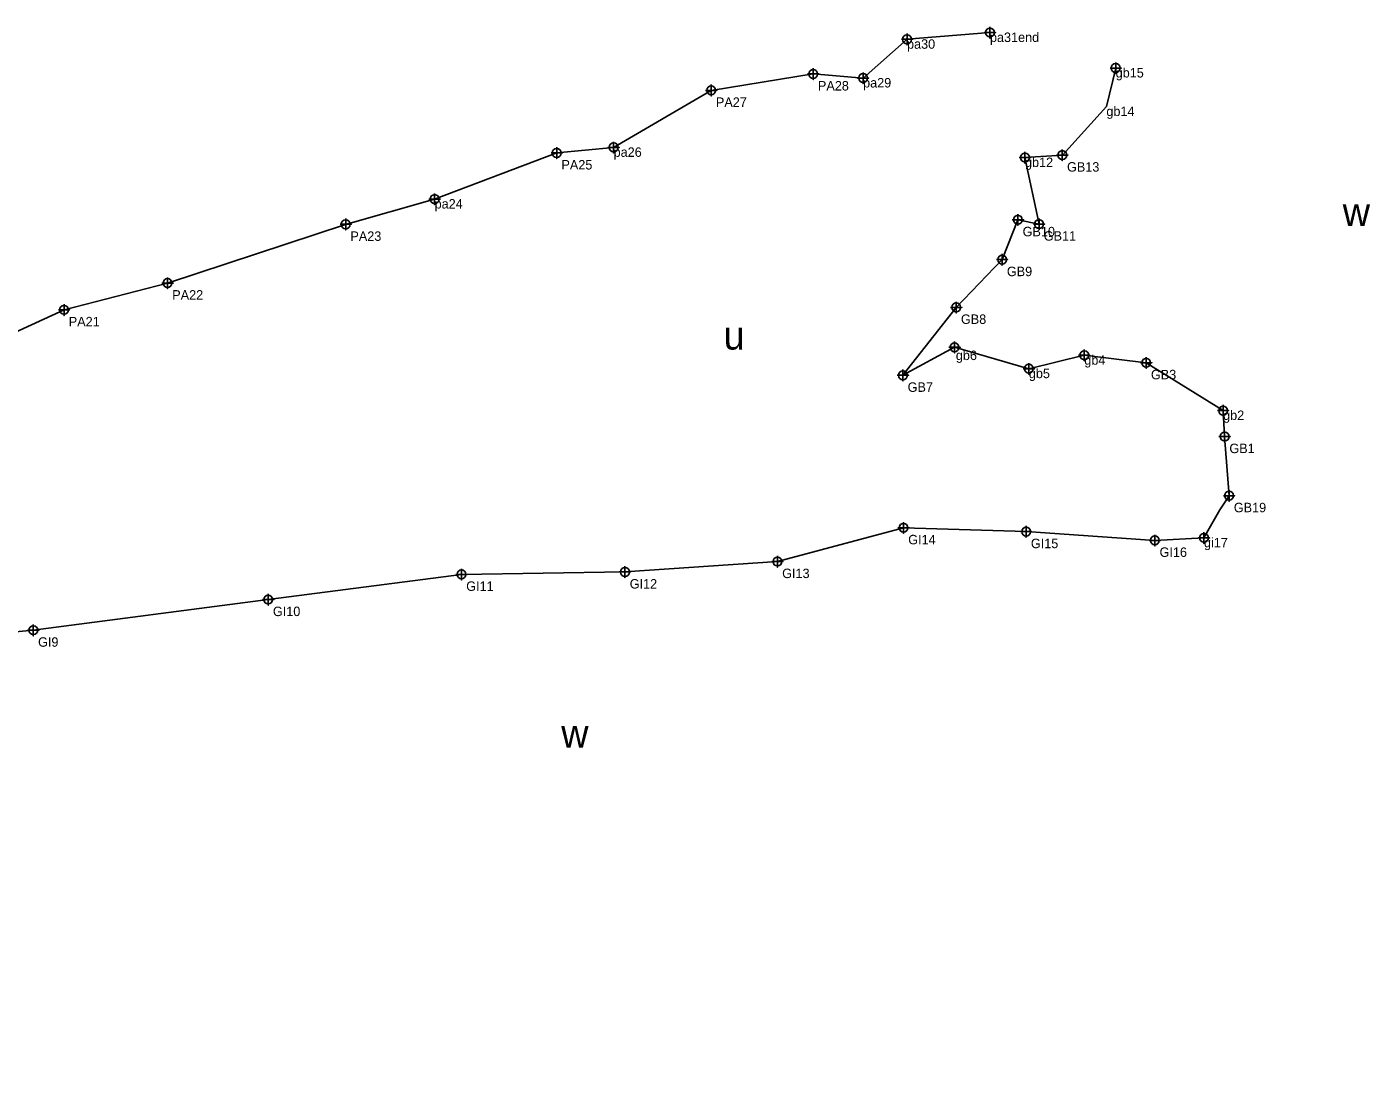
# Model space of a CAD drawing. Extents: x 2184390 to 2187551, y 452846 to 453752.
# Drawn here: x 2186840 to 2187551, y 453193 to 453752 of the extents above; entities that cross this region are included whole.
import ezdxf

# ---------------------------------------------------------------- set-up
doc = ezdxf.new("R2010")
doc.units = 0
for name, color, linetype in [('Exist Environmental Wetland Boundary', 7, 'Continuous'), ('Exist Environmental Wetland Boundary Cogo Comment', 7, 'Continuous'), ('Exist Environmental Wetland Boundary Cogo Point CELL', 7, 'Continuous'), ('Old_Level_20', 7, 'Continuous'), ('Old_Level_52', 7, 'Continuous')]:
    doc.layers.add(name, color=color, linetype=linetype)

msp = doc.modelspace()

# ---------------------------------------------------------------- linework, layer by layer
at = {"layer": 'Exist Environmental Wetland Boundary'}
for points in [[(2186825.25, 453586.6), (2186859.95, 453602.41), (2186914.68, 453616.56), (2187008.89, 453647.61), (2187055.94, 453660.98), (2187120.52, 453685.38), (2187150.61, 453688.32), (2187202.21, 453718.49), (2187256.17, 453727.15), (2187282.56, 453725), (2187305.8, 453745.49), (2187349.64, 453749.06)], [(2187476.13, 453504.11), (2187473.78, 453535.38), (2187472.97, 453549.14), (2187432.29, 453574.42), (2187399.56, 453578.39), (2187370.22, 453571.28), (2187330.92, 453582.59), (2187303.63, 453567.79), (2187331.81, 453603.71), (2187356.1, 453628.96), (2187364.42, 453650.04), (2187375.61, 453647.76), (2187368.19, 453682.93), (2187387.95, 453684.27), (2187411.24, 453709.91), (2187416.15, 453730.28)], [(2186590.17, 453193.44), (2186576.37, 453212.42), (2186571.99, 453259.45), (2186574.44, 453309.06), (2186581.86, 453375.55), (2186597.55, 453411.45), (2186689.52, 453421.44), (2186746.86, 453423.8), (2186843.7, 453432.98), (2186967.92, 453449.19), (2187070.14, 453462.52), (2187156.63, 453463.76), (2187237.25, 453469.29), (2187303.93, 453487.14), (2187368.79, 453485.11), (2187436.86, 453480.5), (2187462.85, 453481.82), (2187471.15, 453496.67), (2187476.13, 453504.11)]]:
    msp.add_lwpolyline(points, dxfattribs=at)
at = {"layer": 'Exist Environmental Wetland Boundary Cogo Point CELL'}
for points in [[(2187349.64, 453752.06), (2187349.64, 453746.06), (2187349.64, 453749.06), (2187352.64, 453749.06), (2187346.64, 453749.06)], [(2187305.8, 453748.49), (2187305.8, 453742.49), (2187305.8, 453745.49), (2187308.8, 453745.49), (2187302.8, 453745.49)], [(2187256.17, 453730.15), (2187256.17, 453724.15), (2187256.17, 453727.15), (2187259.17, 453727.15), (2187253.17, 453727.15)], [(2187416.15, 453733.28), (2187416.15, 453727.28), (2187416.15, 453730.28), (2187419.15, 453730.28), (2187413.15, 453730.28)], [(2187282.56, 453728), (2187282.56, 453722), (2187282.56, 453725), (2187285.56, 453725), (2187279.56, 453725)], [(2187202.21, 453721.49), (2187202.21, 453715.49), (2187202.21, 453718.49), (2187205.21, 453718.49), (2187199.21, 453718.49)], [(2187120.52, 453688.38), (2187120.52, 453682.38), (2187120.52, 453685.38), (2187123.52, 453685.38), (2187117.52, 453685.38)], [(2187150.61, 453691.32), (2187150.61, 453685.32), (2187150.61, 453688.32), (2187153.61, 453688.32), (2187147.61, 453688.32)], [(2187387.92, 453687.25), (2187387.92, 453681.25), (2187387.92, 453684.25), (2187390.92, 453684.25), (2187384.92, 453684.25)], [(2187368.19, 453685.93), (2187368.19, 453679.93), (2187368.19, 453682.93), (2187371.19, 453682.93), (2187365.19, 453682.93)], [(2187055.94, 453663.98), (2187055.94, 453657.98), (2187055.94, 453660.98), (2187058.94, 453660.98), (2187052.94, 453660.98)], [(2187364.43, 453653.05), (2187364.43, 453647.05), (2187364.43, 453650.05), (2187367.43, 453650.05), (2187361.43, 453650.05)], [(2187008.9, 453650.63), (2187008.9, 453644.63), (2187008.9, 453647.63), (2187011.9, 453647.63), (2187005.9, 453647.63)], [(2187375.61, 453650.76), (2187375.61, 453644.76), (2187375.61, 453647.76), (2187378.61, 453647.76), (2187372.61, 453647.76)], [(2187356.1, 453631.96), (2187356.1, 453625.96), (2187356.1, 453628.96), (2187359.1, 453628.96), (2187353.1, 453628.96)], [(2186914.68, 453619.56), (2186914.68, 453613.56), (2186914.68, 453616.56), (2186917.68, 453616.56), (2186911.68, 453616.56)], [(2186859.95, 453605.41), (2186859.95, 453599.41), (2186859.95, 453602.41), (2186862.95, 453602.41), (2186856.95, 453602.41)], [(2187331.81, 453606.71), (2187331.81, 453600.71), (2187331.81, 453603.71), (2187334.81, 453603.71), (2187328.81, 453603.71)], [(2187330.92, 453585.58), (2187330.92, 453579.58), (2187330.92, 453582.58), (2187333.92, 453582.58), (2187327.92, 453582.58)], [(2187399.56, 453581.39), (2187399.56, 453575.39), (2187399.56, 453578.39), (2187402.56, 453578.39), (2187396.56, 453578.39)], [(2187370.22, 453574.28), (2187370.22, 453568.28), (2187370.22, 453571.28), (2187373.22, 453571.28), (2187367.22, 453571.28)], [(2187432.29, 453577.42), (2187432.29, 453571.42), (2187432.29, 453574.42), (2187435.29, 453574.42), (2187429.29, 453574.42)], [(2187303.62, 453570.79), (2187303.62, 453564.79), (2187303.62, 453567.79), (2187306.62, 453567.79), (2187300.62, 453567.79)], [(2187472.98, 453552.11), (2187472.98, 453546.11), (2187472.98, 453549.11), (2187475.98, 453549.11), (2187469.98, 453549.11)], [(2187473.78, 453538.38), (2187473.78, 453532.38), (2187473.78, 453535.38), (2187476.78, 453535.38), (2187470.78, 453535.38)], [(2187476.13, 453507.11), (2187476.13, 453501.11), (2187476.13, 453504.11), (2187479.13, 453504.11), (2187473.13, 453504.11)], [(2187303.93, 453490.14), (2187303.93, 453484.14), (2187303.93, 453487.14), (2187306.93, 453487.14), (2187300.93, 453487.14)], [(2187368.79, 453488.11), (2187368.79, 453482.11), (2187368.79, 453485.11), (2187371.79, 453485.11), (2187365.79, 453485.11)], [(2187436.86, 453483.5), (2187436.86, 453477.5), (2187436.86, 453480.5), (2187439.86, 453480.5), (2187433.86, 453480.5)], [(2187462.85, 453484.82), (2187462.85, 453478.82), (2187462.85, 453481.82), (2187465.85, 453481.82), (2187459.85, 453481.82)], [(2187156.63, 453466.76), (2187156.63, 453460.76), (2187156.63, 453463.76), (2187159.63, 453463.76), (2187153.63, 453463.76)], [(2187237.25, 453472.29), (2187237.25, 453466.29), (2187237.25, 453469.29), (2187240.25, 453469.29), (2187234.25, 453469.29)], [(2187070.14, 453465.52), (2187070.14, 453459.52), (2187070.14, 453462.52), (2187073.14, 453462.52), (2187067.14, 453462.52)], [(2186967.92, 453452.19), (2186967.92, 453446.19), (2186967.92, 453449.19), (2186970.92, 453449.19), (2186964.92, 453449.19)], [(2186843.7, 453435.98), (2186843.7, 453429.98), (2186843.7, 453432.98), (2186846.7, 453432.98), (2186840.7, 453432.98)]]:
    msp.add_lwpolyline(points, dxfattribs=at)
for centre in [(2187349.64, 453749.06), (2187305.8, 453745.49), (2187416.15, 453730.28), (2187256.17, 453727.15), (2187282.56, 453725), (2187202.21, 453718.49), (2187120.52, 453685.38), (2187150.61, 453688.32), (2187368.19, 453682.93), (2187387.92, 453684.25), (2187055.94, 453660.98), (2187364.43, 453650.05), (2187008.9, 453647.63), (2187375.61, 453647.76), (2187356.1, 453628.96), (2186914.68, 453616.56), (2186859.95, 453602.41), (2187331.81, 453603.71), (2187330.92, 453582.58), (2187399.56, 453578.39), (2187370.22, 453571.28), (2187432.29, 453574.42), (2187303.62, 453567.79), (2187472.98, 453549.11), (2187473.78, 453535.38), (2187476.13, 453504.11), (2187303.93, 453487.14), (2187368.79, 453485.11), (2187436.86, 453480.5), (2187462.85, 453481.82), (2187237.25, 453469.29), (2187070.14, 453462.52), (2187156.63, 453463.76), (2186967.92, 453449.19), (2186843.7, 453432.98)]:
    msp.add_circle(centre, 2.34, dxfattribs=at)
at = {"layer": 'Old_Level_20'}
msp.add_line((2187471.15, 453496.67), (2187471.15, 453496.67), dxfattribs=at)

# ---------------------------------------------------------------- texts
at = {"layer": 'Exist Environmental Wetland Boundary Cogo Comment'}
for s, p in [('pa30', (2187305.8, 453740.49)), ('pa31end', (2187349.64, 453744.06)), ('gb15', (2187416.15, 453725.28)), ('PA28', (2187258.67, 453718.4)), ('pa29', (2187282.56, 453720)), ('PA27', (2187204.71, 453709.74)), ('gb14', (2187411.24, 453704.91)), ('pa26', (2187150.61, 453683.32)), ('PA25', (2187123.02, 453676.63)), ('gb12', (2187368.19, 453677.93)), ('GB13', (2187390.42, 453675.5)), ('pa24', (2187055.94, 453655.98)), ('GB10', (2187366.93, 453641.3)), ('PA23', (2187011.4, 453638.88)), ('GB11', (2187378.11, 453639.01)), ('GB9', (2187358.6, 453620.21)), ('PA22', (2186917.18, 453607.81)), ('PA21', (2186862.45, 453593.66)), ('GB8', (2187334.31, 453594.96)), ('gb6', (2187331.61, 453575.85)), ('gb4', (2187399.56, 453573.39)), ('gb5', (2187370.22, 453566.28)), ('GB3', (2187434.79, 453565.67)), ('GB7', (2187306.12, 453559.04)), ('gb2', (2187472.97, 453544.14)), ('GB1', (2187476.28, 453526.63)), ('GB19', (2187478.63, 453495.36)), ('GI14', (2187306.43, 453478.39)), ('GI15', (2187371.29, 453476.36)), ('gi17', (2187462.85, 453476.82)), ('GI16', (2187439.36, 453471.75)), ('GI12', (2187159.13, 453455.01)), ('GI13', (2187239.75, 453460.54)), ('GI11', (2187072.64, 453453.77)), ('GI10', (2186970.42, 453440.44)), ('GI9', (2186846.2, 453424.23))]:
    msp.add_text(s, height=5, dxfattribs=at).set_placement(p)
at = {"layer": 'Old_Level_52'}
for s, p in [('w', (2187536.2, 453646.74)), ('u', (2187208.79, 453581.4)), ('w', (2187122.86, 453370.88))]:
    msp.add_text(s, height=15, dxfattribs=at).set_placement(p)

doc.saveas('drawing.dxf')
